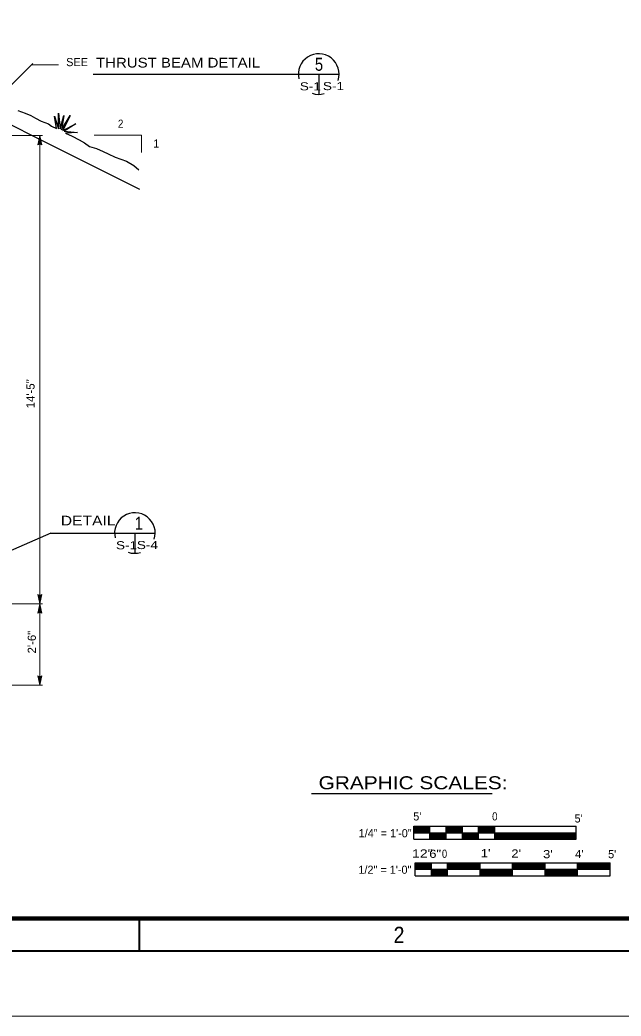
# Model space of a CAD drawing. Extents: x -24.3 to 17.7, y -17.6 to 12.4.
# Drawn here: x -1.17 to 8.07, y -17.61 to -2.28 of the extents above; entities that cross this region are included whole.
import ezdxf
from ezdxf.enums import TextEntityAlignment as Align

# ---------------------------------------------------------------- set-up
doc = ezdxf.new("R2010")
doc.units = 0
doc.header["$LTSCALE"] = 0.05
doc.layers.add('1', color=7, linetype='Continuous', lineweight=13)
doc.layers.add('2', color=7, linetype='Continuous', lineweight=13)

msp = doc.modelspace()

# ---------------------------------------------------------------- linework, layer by layer
at = {"layer": '1'}
for p, q in [((-3.43569, -5.3886), (-0.97569, -2.9496)), ((-0.99669, -2.9696), (-0.58169, -2.9696)), ((-9.90969, -4.0576), (-0.82769, -4.0576)), ((-0.86869, -4.0586), (-0.89969, -4.2026)), ((-0.86869, -4.0956), (-0.88869, -4.1896)), ((-0.86869, -4.1316), (-0.87769, -4.1766)), ((-0.86869, -4.0586), (-0.83769, -4.2026)), ((-0.86869, -4.0956), (-0.84869, -4.1896)), ((-0.86869, -4.1316), (-0.85869, -4.1766)), ((-0.03269, -4.0516), (0.69431, -4.0516)), ((0.69431, -4.0516), (0.69431, -4.3206)), ((-0.86869, -4.1806), (-0.88869, -4.1896)), ((-0.86869, -4.1726), (-0.87769, -4.1766)), ((-0.85869, -4.1766), (-0.86869, -4.1726)), ((-0.84869, -4.1896), (-0.86869, -4.1806)), ((-0.86869, -11.2666), (-0.89969, -11.1226)), ((-0.86869, -11.2296), (-0.88869, -11.1356)), ((-0.88869, -11.1356), (-0.86869, -11.1446)), ((-0.86869, -11.1936), (-0.87869, -11.1486)), ((-0.87869, -11.1486), (-0.86869, -11.1526)), ((-0.86869, -11.2666), (-0.83769, -11.1226)), ((-0.86869, -11.2296), (-0.84869, -11.1356)), ((-0.86869, -11.1446), (-0.84869, -11.1356)), ((-0.86869, -11.1936), (-0.85969, -11.1486)), ((-0.86869, -11.1526), (-0.85969, -11.1486)), ((-3.23169, -11.2666), (-0.82769, -11.2666)), ((-0.86869, -11.2666), (-0.89969, -11.4106)), ((-0.86869, -11.3036), (-0.88869, -11.3976)), ((-0.86869, -11.3396), (-0.87769, -11.3846)), ((-0.86869, -11.2666), (-0.83769, -11.4106)), ((-0.86869, -11.3036), (-0.84869, -11.3976)), ((-0.86869, -11.3396), (-0.85869, -11.3846)), ((-0.86869, -11.3886), (-0.88869, -11.3976)), ((-0.86869, -11.3806), (-0.87769, -11.3846)), ((-0.85869, -11.3846), (-0.86869, -11.3806)), ((-0.84869, -11.3976), (-0.86869, -11.3886)), ((-0.86869, -12.5166), (-0.89969, -12.3726)), ((-0.86869, -12.4796), (-0.88869, -12.3856)), ((-0.88869, -12.3856), (-0.86869, -12.3946)), ((-0.86869, -12.4436), (-0.87869, -12.3986)), ((-0.87869, -12.3986), (-0.86869, -12.4026)), ((-0.86869, -12.5166), (-0.83769, -12.3726)), ((-0.86869, -12.4796), (-0.84869, -12.3856)), ((-0.86869, -12.3946), (-0.84869, -12.3856)), ((-0.86869, -12.4436), (-0.85969, -12.3986)), ((-0.86869, -12.4026), (-0.85969, -12.3986)), ((-2.50469, -12.5166), (-0.82769, -12.5166)), ((17.65731, -17.6106), (-24.34269, -17.6106))]:
    msp.add_line(p, q, dxfattribs=at)
at = {"layer": '1', "lineweight": 25}
for p, q in [((-0.04569, -3.1116), (3.73431, -3.1116)), ((-0.69869, -10.1756), (-2.77669, -11.0896)), ((3.31231, -14.1826), (6.09231, -14.1826)), ((4.88331, -14.6886), (7.38331, -14.6886)), ((4.88331, -14.8886), (4.88331, -14.6886)), ((4.88331, -14.6926), (5.13331, -14.6926)), ((4.88331, -14.6976), (5.13331, -14.6976)), ((4.88331, -14.7026), (5.13331, -14.7026)), ((4.88331, -14.7076), (5.13331, -14.7076)), ((4.88331, -14.7126), (5.13331, -14.7126)), ((4.88331, -14.7176), (5.13331, -14.7176)), ((5.13331, -14.8886), (5.13331, -14.6886)), ((5.38331, -14.8886), (5.38331, -14.6886)), ((5.38331, -14.6926), (5.63331, -14.6926)), ((5.38331, -14.6976), (5.63331, -14.6976)), ((5.38331, -14.7026), (5.63331, -14.7026)), ((5.38331, -14.7076), (5.63331, -14.7076)), ((5.38331, -14.7126), (5.63331, -14.7126)), ((5.38331, -14.7176), (5.63331, -14.7176)), ((5.63331, -14.8886), (5.63331, -14.6886)), ((5.88331, -14.8886), (5.88331, -14.6886)), ((5.88331, -14.6926), (6.13331, -14.6926)), ((5.88331, -14.6976), (6.13331, -14.6976)), ((5.88331, -14.7026), (6.13331, -14.7026)), ((5.88331, -14.7076), (6.13331, -14.7076)), ((5.88331, -14.7126), (6.13331, -14.7126)), ((5.88331, -14.7176), (6.13331, -14.7176)), ((6.13331, -14.8886), (6.13331, -14.6886)), ((7.38331, -14.8886), (7.38331, -14.6886)), ((4.88331, -14.7226), (5.13331, -14.7226)), ((4.88331, -14.7276), (5.13331, -14.7276)), ((4.88331, -14.7326), (5.13331, -14.7326)), ((4.88331, -14.7376), (5.13331, -14.7376)), ((4.88331, -14.7426), (5.13331, -14.7426)), ((4.88331, -14.7476), (5.13331, -14.7476)), ((4.88331, -14.7526), (5.13331, -14.7526)), ((4.88331, -14.7576), (5.13331, -14.7576)), ((4.88331, -14.7626), (5.13331, -14.7626)), ((4.88331, -14.7676), (5.13331, -14.7676)), ((4.88331, -14.7726), (5.13331, -14.7726)), ((4.88331, -14.7776), (5.13331, -14.7776)), ((4.88331, -14.7826), (5.13331, -14.7826)), ((4.88331, -14.7886), (7.38331, -14.7886)), ((5.13331, -14.7946), (5.38331, -14.7946)), ((5.13331, -14.8006), (5.38331, -14.8006)), ((5.13331, -14.8066), (5.38331, -14.8066)), ((5.13331, -14.8146), (5.38331, -14.8146)), ((5.13331, -14.8226), (5.38331, -14.8226)), ((5.13331, -14.8296), (5.38331, -14.8296)), ((5.13331, -14.8376), (5.38331, -14.8376)), ((5.13331, -14.8466), (5.38331, -14.8466)), ((5.13331, -14.8536), (5.38331, -14.8536)), ((5.13331, -14.8626), (5.38331, -14.8626)), ((5.13331, -14.8706), (5.38331, -14.8706)), ((5.38331, -14.7226), (5.63331, -14.7226)), ((5.38331, -14.7276), (5.63331, -14.7276)), ((5.38331, -14.7326), (5.63331, -14.7326)), ((5.38331, -14.7376), (5.63331, -14.7376)), ((5.38331, -14.7426), (5.63331, -14.7426)), ((5.38331, -14.7476), (5.63331, -14.7476)), ((5.38331, -14.7526), (5.63331, -14.7526)), ((5.38331, -14.7576), (5.63331, -14.7576)), ((5.38331, -14.7626), (5.63331, -14.7626)), ((5.38331, -14.7676), (5.63331, -14.7676)), ((5.38331, -14.7726), (5.63331, -14.7726)), ((5.38331, -14.7776), (5.63331, -14.7776)), ((5.38331, -14.7826), (5.63331, -14.7826)), ((5.63331, -14.7946), (5.88331, -14.7946)), ((5.63331, -14.8006), (5.88331, -14.8006)), ((5.63331, -14.8066), (5.88331, -14.8066)), ((5.63331, -14.8146), (5.88331, -14.8146)), ((5.63331, -14.8226), (5.88331, -14.8226)), ((5.63331, -14.8296), (5.88331, -14.8296)), ((5.63331, -14.8376), (5.88331, -14.8376)), ((5.63331, -14.8466), (5.88331, -14.8466)), ((5.63331, -14.8536), (5.88331, -14.8536)), ((5.63331, -14.8626), (5.88331, -14.8626)), ((5.63331, -14.8706), (5.88331, -14.8706)), ((5.88331, -14.7226), (6.13331, -14.7226)), ((5.88331, -14.7276), (6.13331, -14.7276)), ((5.88331, -14.7326), (6.13331, -14.7326)), ((5.88331, -14.7376), (6.13331, -14.7376)), ((5.88331, -14.7426), (6.13331, -14.7426)), ((5.88331, -14.7476), (6.13331, -14.7476)), ((5.88331, -14.7526), (6.13331, -14.7526)), ((5.88331, -14.7576), (6.13331, -14.7576)), ((5.88331, -14.7626), (6.13331, -14.7626)), ((5.88331, -14.7676), (6.13331, -14.7676)), ((5.88331, -14.7726), (6.13331, -14.7726)), ((5.88331, -14.7776), (6.13331, -14.7776)), ((5.88331, -14.7826), (6.13331, -14.7826)), ((6.13331, -14.7946), (7.38331, -14.7946)), ((6.13331, -14.7976), (7.38331, -14.7976)), ((6.13331, -14.8036), (7.38331, -14.8036)), ((6.13331, -14.8086), (7.38331, -14.8086)), ((6.13331, -14.8156), (7.38331, -14.8156)), ((6.13331, -14.8206), (7.38331, -14.8206)), ((6.13331, -14.8286), (7.38331, -14.8286)), ((6.13331, -14.8346), (7.38331, -14.8346)), ((6.13331, -14.8426), (7.38331, -14.8426)), ((6.13331, -14.8476), (7.38331, -14.8476)), ((6.13331, -14.8546), (7.38331, -14.8546)), ((6.13331, -14.8606), (7.38331, -14.8606)), ((6.13331, -14.8656), (7.38331, -14.8656)), ((6.13331, -14.8716), (7.38331, -14.8716)), ((4.88331, -14.8886), (7.38331, -14.8886)), ((5.13331, -14.8776), (5.38331, -14.8776)), ((5.63331, -14.8776), (5.88331, -14.8776)), ((6.13331, -14.8776), (7.38331, -14.8776)), ((4.90631, -15.2506), (7.90631, -15.2506)), ((4.90631, -15.4506), (4.90631, -15.2506)), ((4.90631, -15.2556), (5.15631, -15.2556)), ((4.90631, -15.2606), (5.15631, -15.2606)), ((4.90631, -15.2656), (5.15631, -15.2656)), ((4.90631, -15.2706), (5.15631, -15.2706)), ((4.90631, -15.2756), (5.15631, -15.2756)), ((4.90631, -15.2806), (5.15631, -15.2806)), ((4.90631, -15.2856), (5.15631, -15.2856)), ((4.90631, -15.2906), (5.15631, -15.2906)), ((4.90631, -15.2956), (5.15631, -15.2956)), ((4.90631, -15.3006), (5.15631, -15.3006)), ((4.90631, -15.3056), (5.15631, -15.3056)), ((4.90631, -15.3106), (5.15631, -15.3106)), ((4.90631, -15.3156), (5.15631, -15.3156)), ((4.90631, -15.3206), (5.15631, -15.3206)), ((4.90631, -15.3256), (5.15631, -15.3256)), ((4.90631, -15.3306), (5.15631, -15.3306)), ((5.15631, -15.4506), (5.15631, -15.2506)), ((5.40631, -15.4506), (5.40631, -15.2506)), ((5.40631, -15.2556), (5.90631, -15.2556)), ((5.40631, -15.2606), (5.90631, -15.2606)), ((5.40631, -15.2656), (5.90631, -15.2656)), ((5.40631, -15.2706), (5.90631, -15.2706)), ((5.40631, -15.2756), (5.90631, -15.2756)), ((5.40631, -15.2806), (5.90631, -15.2806)), ((5.40631, -15.2856), (5.90631, -15.2856)), ((5.40631, -15.2906), (5.90631, -15.2906)), ((5.40631, -15.2956), (5.90631, -15.2956)), ((5.40631, -15.3006), (5.90631, -15.3006)), ((5.40631, -15.3056), (5.90631, -15.3056)), ((5.40631, -15.3106), (5.90631, -15.3106)), ((5.40631, -15.3156), (5.90631, -15.3156)), ((5.40631, -15.3206), (5.90631, -15.3206)), ((5.40631, -15.3256), (5.90631, -15.3256)), ((5.40631, -15.3306), (5.90631, -15.3306)), ((5.90631, -15.4506), (5.90631, -15.2506)), ((6.40631, -15.4506), (6.40631, -15.2506)), ((6.40631, -15.2556), (6.90631, -15.2556)), ((6.40631, -15.2606), (6.90631, -15.2606)), ((6.40631, -15.2656), (6.90631, -15.2656)), ((6.40631, -15.2706), (6.90631, -15.2706)), ((6.40631, -15.2756), (6.90631, -15.2756)), ((6.40631, -15.2806), (6.90631, -15.2806)), ((6.40631, -15.2856), (6.90631, -15.2856)), ((6.40631, -15.2906), (6.90631, -15.2906)), ((6.40631, -15.2956), (6.90631, -15.2956)), ((6.40631, -15.3006), (6.90631, -15.3006)), ((6.40631, -15.3056), (6.90631, -15.3056)), ((6.40631, -15.3106), (6.90631, -15.3106)), ((6.40631, -15.3156), (6.90631, -15.3156)), ((6.40631, -15.3206), (6.90631, -15.3206)), ((6.40631, -15.3256), (6.90631, -15.3256)), ((6.40631, -15.3306), (6.90631, -15.3306)), ((6.90631, -15.4506), (6.90631, -15.2506)), ((7.40631, -15.4506), (7.40631, -15.2506)), ((7.40631, -15.2556), (7.90631, -15.2556)), ((7.40631, -15.2606), (7.90631, -15.2606)), ((7.40631, -15.2656), (7.90631, -15.2656)), ((7.40631, -15.2706), (7.90631, -15.2706)), ((7.40631, -15.2756), (7.90631, -15.2756)), ((7.40631, -15.2806), (7.90631, -15.2806)), ((7.40631, -15.2856), (7.90631, -15.2856)), ((7.40631, -15.2906), (7.90631, -15.2906)), ((7.40631, -15.2956), (7.90631, -15.2956)), ((7.40631, -15.3006), (7.90631, -15.3006)), ((7.40631, -15.3056), (7.90631, -15.3056)), ((7.40631, -15.3106), (7.90631, -15.3106)), ((7.40631, -15.3156), (7.90631, -15.3156)), ((7.40631, -15.3206), (7.90631, -15.3206)), ((7.40631, -15.3256), (7.90631, -15.3256)), ((7.40631, -15.3306), (7.90631, -15.3306)), ((7.90631, -15.4506), (7.90631, -15.2506)), ((4.90631, -15.3356), (5.15631, -15.3356)), ((4.90631, -15.3406), (5.15631, -15.3406)), ((4.90631, -15.3456), (5.15631, -15.3456)), ((4.90631, -15.3506), (7.90631, -15.3506)), ((4.90631, -15.4506), (7.90631, -15.4506)), ((5.15631, -15.3556), (5.40631, -15.3556)), ((5.15631, -15.3606), (5.40631, -15.3606)), ((5.15631, -15.3656), (5.40631, -15.3656)), ((5.15631, -15.3706), (5.40631, -15.3706)), ((5.15631, -15.3756), (5.40631, -15.3756)), ((5.15631, -15.3806), (5.40631, -15.3806)), ((5.15631, -15.3856), (5.40631, -15.3856)), ((5.15631, -15.3906), (5.40631, -15.3906)), ((5.15631, -15.3956), (5.40631, -15.3956)), ((5.15631, -15.4006), (5.40631, -15.4006)), ((5.15631, -15.4056), (5.40631, -15.4056)), ((5.15631, -15.4106), (5.40631, -15.4106)), ((5.15631, -15.4156), (5.40631, -15.4156)), ((5.15631, -15.4206), (5.40631, -15.4206)), ((5.15631, -15.4256), (5.40631, -15.4256)), ((5.15631, -15.4306), (5.40631, -15.4306)), ((5.15631, -15.4356), (5.40631, -15.4356)), ((5.15631, -15.4406), (5.40631, -15.4406)), ((5.15631, -15.4456), (5.40631, -15.4456)), ((5.40631, -15.3356), (5.90631, -15.3356)), ((5.40631, -15.3406), (5.90631, -15.3406)), ((5.40631, -15.3456), (5.90631, -15.3456)), ((5.90631, -15.3556), (6.40631, -15.3556)), ((5.90631, -15.3606), (6.40631, -15.3606)), ((5.90631, -15.3656), (6.40631, -15.3656)), ((5.90631, -15.3706), (6.40631, -15.3706)), ((5.90631, -15.3756), (6.40631, -15.3756)), ((5.90631, -15.3806), (6.40631, -15.3806)), ((5.90631, -15.3856), (6.40631, -15.3856)), ((5.90631, -15.3906), (6.40631, -15.3906)), ((5.90631, -15.3956), (6.40631, -15.3956)), ((5.90631, -15.4006), (6.40631, -15.4006)), ((5.90631, -15.4056), (6.40631, -15.4056)), ((5.90631, -15.4106), (6.40631, -15.4106)), ((5.90631, -15.4156), (6.40631, -15.4156)), ((5.90631, -15.4206), (6.40631, -15.4206)), ((5.90631, -15.4256), (6.40631, -15.4256)), ((5.90631, -15.4306), (6.40631, -15.4306)), ((5.90631, -15.4356), (6.40631, -15.4356)), ((5.90631, -15.4406), (6.40631, -15.4406)), ((5.90631, -15.4456), (6.40631, -15.4456)), ((6.40631, -15.3356), (6.90631, -15.3356)), ((6.40631, -15.3406), (6.90631, -15.3406)), ((6.40631, -15.3456), (6.90631, -15.3456)), ((6.90631, -15.3556), (7.40631, -15.3556)), ((6.90631, -15.3606), (7.40631, -15.3606)), ((6.90631, -15.3656), (7.40631, -15.3656)), ((6.90631, -15.3706), (7.40631, -15.3706)), ((6.90631, -15.3756), (7.40631, -15.3756)), ((6.90631, -15.3806), (7.40631, -15.3806)), ((6.90631, -15.3856), (7.40631, -15.3856)), ((6.90631, -15.3906), (7.40631, -15.3906)), ((6.90631, -15.3956), (7.40631, -15.3956)), ((6.90631, -15.4006), (7.40631, -15.4006)), ((6.90631, -15.4056), (7.40631, -15.4056)), ((6.90631, -15.4106), (7.40631, -15.4106)), ((6.90631, -15.4156), (7.40631, -15.4156)), ((6.90631, -15.4206), (7.40631, -15.4206)), ((6.90631, -15.4256), (7.40631, -15.4256)), ((6.90631, -15.4306), (7.40631, -15.4306)), ((6.90631, -15.4356), (7.40631, -15.4356)), ((6.90631, -15.4406), (7.40631, -15.4406)), ((6.90631, -15.4456), (7.40631, -15.4456)), ((7.40631, -15.3356), (7.90631, -15.3356)), ((7.40631, -15.3406), (7.90631, -15.3406)), ((7.40631, -15.3456), (7.90631, -15.3456))]:
    msp.add_line(p, q, dxfattribs=at)
at = {"layer": '1', "lineweight": 40}
msp.add_line((0.65731, -16.1106), (0.65731, -16.6106), dxfattribs=at)
msp.add_lwpolyline([(-23.34269, -16.6106), (-23.34269, 11.3894), (16.65731, 11.3894), (16.65731, -16.6106)], close=True, dxfattribs=at)
at = {"layer": '1', "lineweight": 90}
msp.add_lwpolyline([(-21.84269, 10.8894), (16.15731, 10.8894), (16.15731, -16.1106), (-21.84269, -16.1106)], close=True, dxfattribs=at)
at = {"layer": '1', "lineweight": 25}
for points in [[(-9.91169, -3.0386), (-2.92769, -3.0886), (0.66231, -4.8826)], [(-1.20969, -3.6696), (-1.09569, -3.7136), (-1.00769, -3.7466), (-0.93469, -3.7906), (-0.84669, -3.8386), (-0.73669, -3.8796), (-0.68869, -3.9156), (-0.61169, -3.9486), (-0.64469, -3.7616), (-0.58169, -3.9566), (-0.58169, -3.7136), (-0.55669, -3.9566), (-0.50169, -3.7466), (-0.53469, -3.9676), (-0.40269, -3.7466), (-0.51269, -3.9786), (-0.31369, -3.8796), (-0.49369, -3.9926), (-0.29169, -4.0116), (-0.47169, -4.0226), (-0.37269, -4.0666), (-0.26269, -4.1256), (-0.18169, -4.1696), (-0.10469, -4.2246), (0.00131, -4.2576), (0.10431, -4.3016), (0.18131, -4.3416), (0.28831, -4.3896), (0.46431, -4.4516), (0.57831, -4.5176), (0.65531, -4.5876)]]:
    msp.add_lwpolyline(points, dxfattribs=at)
at = {"layer": '1'}
for points in [[(-0.86869, -12.5166), (-0.86869, -11.2666), (-0.86869, -4.0586)], [(-0.83769, -4.2026), (-0.86869, -4.1886), (-0.89969, -4.2026)], [(-0.89969, -11.1226), (-0.86869, -11.1366), (-0.83769, -11.1226)], [(-0.83769, -11.4106), (-0.86869, -11.3966), (-0.89969, -11.4106)], [(-0.89969, -12.3726), (-0.86869, -12.3866), (-0.83769, -12.3726)]]:
    msp.add_lwpolyline(points, dxfattribs=at)
at = {"layer": '2', "lineweight": 25}
for p, q in [((3.11031, -3.1116), (3.73431, -3.1116)), ((3.42231, -3.1116), (3.42231, -3.4236)), ((-0.69869, -10.1756), (0.28231, -10.1756)), ((0.28231, -10.1756), (0.90631, -10.1756)), ((0.59431, -10.1756), (0.59431, -10.4876))]:
    msp.add_line(p, q, dxfattribs=at)
for centre, start, end in [((3.42231, -3.1116), 341.96976, 193.81208), ((3.42231, -3.1116), 251.04049, 285.74671), ((0.59431, -10.1756), 341.96976, 193.81208), ((0.59431, -10.1756), 251.04049, 285.74671)]:
    msp.add_arc(centre, 0.3125, start, end, dxfattribs=at)

# ---------------------------------------------------------------- texts
at = {"layer": '1'}
msp.add_text('SEE', height=0.125, dxfattribs=at).set_placement((-0.46369, -2.9896))
at = {"layer": '1', "width": 1.15}
msp.add_text('THRUST BEAM DETAIL', height=0.15, dxfattribs=at).set_placement((-0.00469, -3.0106))
at = {"layer": '1'}
for s, height, width, p in [('2', 0.125, 0.9, (0.37481, -3.9376)), ('0', 0.125, 0.9, (6.13165, -14.5996)), ("4'", 0.125, 1.05, (7.43066, -15.1796)), ('2', 0.25, 0.9, (4.65781, -16.4856))]:
    msp.add_text(s, height=height, dxfattribs=dict(at, width=width)).set_placement(p, align=Align.CENTER)
for s, p in [('1', (0.9232, -4.2426)), ("5'", (4.93966, -14.5996)), ("5'", (7.42166, -14.6316)), ("5'", (7.93766, -15.1806))]:
    msp.add_text(s, height=0.125, dxfattribs=at).set_placement(p, align=Align.CENTER)
at = {"layer": '1', "width": 1.05}
for s, p in [('14\'-5"', (-0.94969, -8.0326)), ('2\'-6"', (-0.92969, -11.8541))]:
    msp.add_text(s, height=0.125, rotation=90, dxfattribs=at).set_placement(p, align=Align.CENTER)
at = {"layer": '1', "width": 1.2}
for s, height, p in [('DETAIL', 0.15, (0.29631, -10.0596)), ('GRAPHIC SCALES:', 0.2, (6.32731, -14.1196))]:
    msp.add_text(s, height=height, dxfattribs=at).set_placement(p, align=Align.RIGHT)
at = {"layer": '1'}
for s, p in [('1/4" = 1\'-0"', (4.8521, -14.8586)), ('1/2" = 1\'-0"', (4.8481, -15.4206))]:
    msp.add_text(s, height=0.125, dxfattribs=at).set_placement(p, align=Align.RIGHT)
at = {"layer": '2'}
for s, height, width, p in [('5', 0.2, 0.85, (3.42681, -3.0606)), ('S-1', 0.125, 1.25, (3.29331, -3.3626)), ('S-1', 0.125, 1.25, (3.64931, -3.3586)), ('1', 0.2, 0.85, (0.65481, -10.1246)), ('S-1', 0.125, 1.25, (0.46531, -10.4266)), ('S-4', 0.125, 1.25, (0.78631, -10.4226)), ('12"', 0.125, 1.3, (5.01631, -15.1706)), ('6"', 0.125, 1.2, (5.21431, -15.1756)), ('0', 0.125, 0.85, (5.35831, -15.1746)), ("1'", 0.125, 1.2, (5.99131, -15.1656)), ("2'", 0.125, 1.2, (6.46031, -15.1706)), ("3'", 0.125, 1.2, (6.94931, -15.1806))]:
    msp.add_text(s, height=height, dxfattribs=dict(at, width=width)).set_placement(p, align=Align.CENTER)

doc.saveas('drawing.dxf')
